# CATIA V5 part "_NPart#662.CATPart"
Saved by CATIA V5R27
Part number: TCST2103^Endstop_Opto_TCST2103_D‚faut
Revision: ANY
Definition: UNKNOWN
Nomenclature: TCST2103^Endstop_Opto_TCST2103_D‚faut
Source: Unknown
Bounding box of the stored display mesh (mm): x -12.25 to 12.25, y -11 to 0, z -3.175 to 3.175
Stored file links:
  E:\university\my-thesis\My Thesis Publication\Final-Updata\CAD\_NPart#662.CATPart
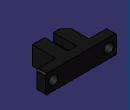
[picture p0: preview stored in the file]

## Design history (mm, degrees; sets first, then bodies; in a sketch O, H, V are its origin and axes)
Body1 "Congé1" (main body)
  Solid1: solid without history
